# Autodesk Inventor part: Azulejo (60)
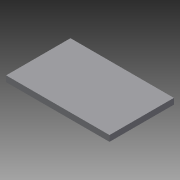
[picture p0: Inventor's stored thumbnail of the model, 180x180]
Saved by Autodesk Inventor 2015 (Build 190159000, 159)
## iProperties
Created: 2015-04
Part Number: Azulejo (60)
Material: Genérico
Document SubType Name: Modeling
Designer: Felipe
Density: 1 g/cm^3
Appearance: Padrão
Author: Felipe
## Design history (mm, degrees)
sketch "Sketch1"
  geometry: L1 (7081.362, 848.164)-(5601.362, 848.164); L2 (5581.362, 748.164)-(4101.362, 748.164); L3 (4081.362, 848.164)-(2601.362, 848.164); L4 (2581.362, 848.164)-(1101.362, 848.164); L5 (7101.362, 848.164)-(7101.362, 908.164); L6 (5601.362, 848.164)-(5601.362, 908.164); L7 (5601.362, 908.164)-(7081.362, 908.164); L8 (4101.362, 748.164)-(4101.362, 908.164); L9 (4101.362, 908.164)-(5581.362, 908.164); L10 (5581.362, 908.164)-(5581.362, 748.164); L11 (2601.362, 848.164)-(2601.362, 908.164); L12 (2601.362, 908.164)-(4081.362, 908.164); L13 (4081.362, 908.164)-(4081.362, 848.164); L14 (7081.362, 908.164)-(7081.362, 848.164); L15 (1101.362, 848.164)-(1101.362, 908.164); L16 (1101.362, 908.164)-(2581.362, 908.164); L17 (2581.362, 908.164)-(2581.362, 848.164); L18 (1081.362, 908.164)-(1081.362, 828.268); L19 (115.504, 828.363)-(115.504, 88.164); L20 (125.504, 828.363)-(125.504, 88.164); L21 (1081.362, 88.164)-(1081.362, 888.164); L22 (7101.362, 888.164)-(7101.362, 848.164); L23 (5601.362, 168.164)-(5601.362, 908.164); L24 (5601.362, 908.164)-(7081.362, 908.164); L25 (7081.362, 888.164)-(7081.362, 848.164); L26 (5581.362, 908.164)-(5181.362, 908.164); L27 (5581.362, 88.164)-(5581.362, 888.164); L28 (4101.362, 908.164)-(5101.362, 908.164); L29 (4101.362, 88.164)-(4101.362, 888.164); L30 (4081.362, 88.164)-(4081.362, 888.164); L31 (4081.362, 908.164)-(2601.362, 908.164); L32 (2601.362, 888.164)-(2601.362, 88.164); L33 (2581.362, 88.164)-(2581.362, 888.164); L34 (2581.362, 908.164)-(1101.362, 908.164); L35 (1101.362, 888.164)-(1101.362, 88.164); L36 (1081.362, 908.164)-(681.362, 908.164); L37 (581.362, 88.164)-(581.362, 68.164); L38 (581.362, 68.164)-(1081.362, 68.164); L39 (1601.362, 88.164)-(1601.362, 68.164); L40 (1601.362, 68.164)-(1101.362, 68.164); L41 (3601.362, 88.164)-(3601.362, 68.164); L42 (3601.362, 68.164)-(2601.362, 68.164); L43 (5161.362, -11.836)-(5161.362, 748.164); L44 (5161.362, 748.164)-(5581.362, 748.164); L45 (5581.362, 748.164)-(5581.362, 88.164); L46 (5581.362, 88.164)-(5161.362, 88.164); L47 (5161.362, 88.164)-(5161.362, 748.164); L48 (1081.362, 68.164)-(125.504, 68.164); L49 (125.504, 68.164)-(125.504, 908.164); L50 (125.504, 908.164)-(1081.362, 908.164); L51 (1081.362, 908.164)-(1081.362, 68.164); L52 (5161.362, 88.164)-(4101.362, 88.164); L53 (4101.362, 88.164)-(4101.362, 748.164); L54 (4101.362, 748.164)-(5161.362, 748.164); L55 (5161.362, 748.164)-(5161.362, 88.164); 2 further points
  constraints: 110 end point, 20 point on line, 6 parallel, 3 horizontal, 3 perpendicular
  dimensions: "d2" = 4101.36173 distance from line of L29 point (0, 0); "d3" = 88.16406 distance from line of point (0, 0) L52; "d4" = 660 distance between parallel lines of L52 L2; "d5" = 1060 distance between parallel lines of L47 L29
extrude "Extrusion1" new body sketch "Sketch1" distance "d0" = 60; taper "d1" = 0 deg
body "Solid1"
